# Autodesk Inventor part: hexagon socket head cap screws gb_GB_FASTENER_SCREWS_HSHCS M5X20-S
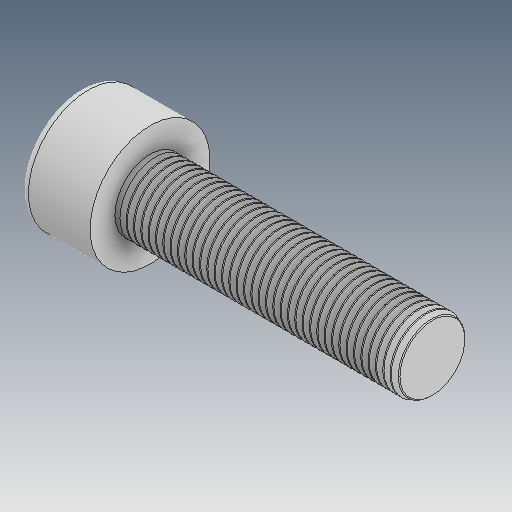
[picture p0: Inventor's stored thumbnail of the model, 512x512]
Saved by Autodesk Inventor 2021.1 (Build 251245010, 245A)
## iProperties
Created: 2015-08
Part Number: hexagon socket head cap screws gb_GB_FASTENER_SCREWS_HSHCS M5X20-S
Material: Ogólny
Document SubType Name: Modeling
Designer: user
Density: 1 g/cm^3
Appearance: Domyślna
Author: user
Revision Number: ÈÎºÎ
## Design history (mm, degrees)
feature "LPattern10"
node "Bryła1"
